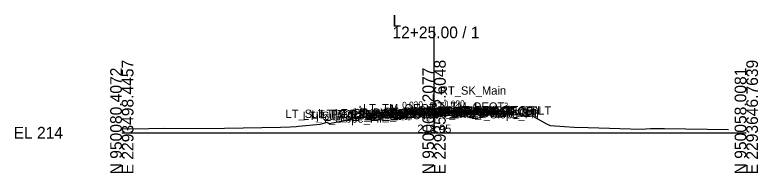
# Model space of a CAD drawing. Extents: x -26 to 7053, y -10 to 7035.
# Drawn here: x -25.7 to 152.8, y 490.3 to 528.3 of the extents above; entities that cross this region are included whole.
import ezdxf

# ---------------------------------------------------------------- set-up
doc = ezdxf.new("R2010")
doc.units = 0
for name, color, linetype in [('Default', 7, 'Continuous'), ('Exist Cross Section Cell', 7, 'Continuous'), ('Exist XS Center Line Elevation Label', 7, 'Continuous'), ('Exist XS Ground Line', 7, 'Continuous'), ('Prop CMT Pvmt Course 1', 7, 'Continuous'), ('Prop CMT Pvmt Course 2', 7, 'Continuous'), ('Prop CMT Pvmt Surface', 7, 'Continuous'), ('Prop CMT Pvmt Surface Overlay', 7, 'Continuous'), ('Prop CMT Pvmt Surface Shoulder', 7, 'Continuous'), ('Prop CMT Shld Paved Course 1', 7, 'Continuous'), ('Prop CMT Shld Paved Course 2', 7, 'Continuous'), ('Prop CMT Slope Grass', 7, 'Continuous'), ('Prop CMT Subgrade Earthwork', 7, 'Continuous'), ('Prop XS EOT Tick Mark', 7, 'Continuous'), ('Prop XS SE Text', 7, 'Continuous'), ('Prop XS Side Slope Text', 7, 'Continuous')]:
    doc.layers.add(name, color=color, linetype=linetype)

msp = doc.modelspace()

# ---------------------------------------------------------------- linework, layer by layer
at = {"layer": 'Exist Cross Section Cell'}
for p, q in [((75, 500), (75, 525.46)), ((0, 500), (75, 500)), ((75, 500), (150, 500))]:
    msp.add_line(p, q, dxfattribs=at)
at = {"layer": 'Exist XS Ground Line'}
for p, q in [((55.28, 503.31), (65.25, 504.5)), ((65.25, 504.5), (74.17, 504.91)), ((74.17, 504.91), (75.18, 504.96)), ((75.18, 504.96), (78.63, 504.99)), ((78.63, 504.99), (84.63, 505.06)), ((84.63, 505.06), (89.78, 504.68)), ((89.78, 504.68), (98.69, 503.98)), ((98.69, 503.98), (101.97, 502.16)), ((42.41, 501.55), (47.63, 502.02)), ((47.63, 502.02), (48.75, 502.38)), ((48.75, 502.38), (49.29, 502.54)), ((49.29, 502.54), (49.81, 502.23)), ((49.81, 502.23), (54.53, 503.18)), ((54.53, 503.18), (54.85, 503.27)), ((54.85, 503.27), (55.28, 503.31)), ((101.97, 502.16), (102.87, 501.74)), ((102.87, 501.74), (106.32, 501.48)), ((0, 500.92), (6.46, 500.99)), ((6.46, 500.99), (10.27, 501.07)), ((10.27, 501.07), (20.21, 500.97)), ((20.21, 500.97), (38.13, 501.31)), ((38.13, 501.31), (40.45, 501.43)), ((40.45, 501.43), (41.85, 501.45)), ((41.85, 501.45), (42.41, 501.55)), ((106.32, 501.48), (108.65, 501.35)), ((108.65, 501.35), (112.01, 501.27)), ((112.01, 501.27), (124.73, 500.87)), ((124.73, 500.87), (126.98, 500.97)), ((126.98, 500.97), (130.32, 501)), ((130.32, 501), (145.7, 500.75))]:
    msp.add_line(p, q, dxfattribs=at)
at = {"layer": 'Prop CMT Pvmt Course 1'}
for points in [[(75, 505.12), (85, 505.32)], [(85, 505.32), (85, 505.07)], [(75, 505.12), (65, 504.81)], [(65, 504.56), (75, 504.87)], [(65, 504.81), (65, 504.56)], [(75, 504.99), (75, 505.12)], [(75, 504.99), (75, 505.12)], [(85, 505.07), (75, 504.87)], [(75, 504.87), (75, 504.99), (75, 504.99)], [(75, 504.87), (75, 504.99), (75, 504.99)]]:
    msp.add_lwpolyline(points, dxfattribs=at)
at = {"layer": 'Prop CMT Pvmt Course 2'}
for points in [[(75, 504.87), (65, 504.56)], [(65, 504.56), (65, 504.23)], [(65, 504.23), (75, 504.53)], [(75, 504.87), (85, 505.07)], [(75, 504.53), (75, 504.87)], [(75, 504.53), (75, 504.87)], [(85, 504.73), (75, 504.53)], [(85, 505.07), (85, 504.73)]]:
    msp.add_lwpolyline(points, dxfattribs=at)
at = {"layer": 'Prop CMT Pvmt Surface'}
for points in [[(75, 505.12), (85, 505.32)], [(75, 505.12), (65, 504.81)]]:
    msp.add_lwpolyline(points, dxfattribs=at)
at = {"layer": 'Prop CMT Pvmt Surface Overlay'}
for points in [[(75, 505.12), (85, 505.32)], [(75, 505.12), (65, 504.81)]]:
    msp.add_lwpolyline(points, dxfattribs=at)
at = {"layer": 'Prop CMT Pvmt Surface Shoulder'}
for points in [[(85, 505.32), (89.1, 505.4)], [(65, 504.81), (60.33, 504.67)]]:
    msp.add_lwpolyline(points, dxfattribs=at)
at = {"layer": 'Prop CMT Shld Paved Course 1'}
for points in [[(85, 505.32), (89.1, 505.4), (89.35, 505.15)], [(85, 505.07), (85, 505.32)], [(65, 504.81), (60.33, 504.67), (60.08, 504.41)], [(60.08, 504.41), (65, 504.56)], [(65, 504.56), (65, 504.81)], [(89.35, 505.15), (85, 505.07)]]:
    msp.add_lwpolyline(points, dxfattribs=at)
at = {"layer": 'Prop CMT Shld Paved Course 2'}
for points in [[(65, 504.56), (60.08, 504.41), (59.58, 504.4), (59.23, 504.05)], [(59.23, 504.05), (65, 504.23)], [(65, 504.23), (65, 504.56)], [(85, 505.07), (89.35, 505.15), (89.85, 505.16), (90.18, 504.84)], [(85, 504.73), (85, 505.07)], [(90.18, 504.84), (85, 504.73)]]:
    msp.add_lwpolyline(points, dxfattribs=at)
at = {"layer": 'Prop CMT Slope Grass'}
for points in [[(89.1, 505.4), (91.13, 505.32)], [(91.13, 505.32), (92.89, 504.43)], [(58.32, 504.51), (56.13, 503.41)], [(60.33, 504.67), (58.32, 504.51)]]:
    msp.add_lwpolyline(points, dxfattribs=at)
at = {"layer": 'Prop CMT Subgrade Earthwork'}
for points in [[(90.18, 504.84), (90.68, 505.34)], [(59.23, 504.05), (58.74, 504.54)], [(65, 504.23), (59.23, 504.05)], [(75, 504.53), (65, 504.23)], [(75, 504.53), (85, 504.73)], [(85, 504.73), (90.18, 504.84)]]:
    msp.add_lwpolyline(points, dxfattribs=at)
at = {"layer": 'Prop XS EOT Tick Mark'}
for p, q in [((85, 505.31), (85, 507.22)), ((65, 504.81), (65, 506.72))]:
    msp.add_line(p, q, dxfattribs=at)

# ---------------------------------------------------------------- texts
at = {"layer": 'Default'}
for s, height, p in [('RT_SK_Main', 2, (76.4, 509.12)), ('RT_TM_OEOT', 2, (73.9, 505.28)), ('LT_Sub_Trench_Out_DLT', 2, (39.31, 503.54)), ('LT_PS2_Shelf_Out', 2, (45.56, 503.4)), ('LT_GS_OS_CTL', 2, (47.69, 503.51)), ('LT_PS2_OEOP', 2, (50.31, 503.41)), ('LT_PS1_OEOP', 2, (51.14, 503.67)), ('LT_Sub_OEOT', 2, (55.08, 503.23)), ('LT_PV2_OEOT', 2, (55.17, 503.56)), ('LT_PV1_OEOT', 2, (55.74, 503.81)), ('LT_TM_OEOT', 2, (57.94, 504.87)), ('RT_PV1_OEEOP_W', 2, (62.94, 503.99)), ('LT_PV1_OEEOP_W', 2, (62.98, 503.99)), ('RT_Sub_OEEOP', 2, (64.17, 503.53)), ('LT_Sub_OEEOP', 2, (64.21, 503.53)), ('RT_PV2_OEEOP', 2, (64.26, 503.87)), ('LT_PV2_OEEOP', 2, (64.31, 503.87)), ('PV1_PGL_W', 2, (67.58, 503.99)), ('PV1_PGL', 2, (69.47, 504.12)), ('RT_Sub_Trench_Out_DLT', 2, (71.2, 504.34)), ('RT_Sub_Trench_Out', 2, (74.33, 503.84)), ('RT_Sub_OEOT', 2, (75.03, 503.73)), ('RT_PV2_OEOT', 2, (75.13, 504.07)), ('RT_PV1_OEOT', 2, (75.69, 504.32)), ('RT_PS2_Shelf_Out', 2, (75.79, 504.16)), ('RT_PS2_OEOP', 2, (79.54, 504.15)), ('RT_PS1_OEOP', 2, (79.86, 504.4)), ('RT_GS_OS_CTL', 2, (80.45, 504.32)), ('RT_Slope_Fill', 2, (83.37, 503.43)), ('LT_Sub_Trench_Out', 2, (43.44, 503.05)), ('LT_Slope_Fill', 2, (46.65, 502.41)), ('-', 0.0001, (0, 500))]:
    msp.add_text(s, height=height, dxfattribs=at).set_placement(p)
at = {"layer": 'Exist Cross Section Cell'}
for s, p in [('L', (65, 525.46)), ('12+25.00 / 1', (65, 522.66)), ('EL 214', (-26, 498.6))]:
    msp.add_text(s, height=2.8, dxfattribs=at).set_placement(p)
for s, p in [('E 2293498.4457', (2.8, 490)), ('E 2293572.6048', (77.8, 490)), ('E 2293646.7639', (152.8, 490)), ('N 950080.4072', (0, 490)), ('N 950069.2077', (75, 490)), ('N 950058.0081', (150, 490))]:
    msp.add_text(s, height=2.8, rotation=90, dxfattribs=at).set_placement(p)
at = {"layer": 'Exist XS Center Line Elevation Label'}
msp.add_text('218.95', height=2, dxfattribs=at).set_placement((70.98, 499.95))
at = {"layer": 'Prop XS SE Text'}
for s, rotation, p in [('0.030', 1.7404, (67.35, 505.88)), ('0.020', 1.1458, (77.36, 506.16))]:
    msp.add_text(s, height=1.5, rotation=rotation, dxfattribs=at).set_placement(p)
at = {"layer": 'Prop XS Side Slope Text'}
for rotation, p in [(333.4349, (91.28, 506.08)), (26.5651, (55.83, 504.1))]:
    msp.add_text('2:1', height=1.5, rotation=rotation, dxfattribs=at).set_placement(p)

doc.saveas('drawing.dxf')
